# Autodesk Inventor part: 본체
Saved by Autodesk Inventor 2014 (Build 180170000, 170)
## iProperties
Created: 2026-09
Part Number: 본체
Material: 일반
Document SubType Name: Modeling
Designer: dg
Density: 1 g/cm^3
Appearance: 기본값
Author: dg
Author: jhkim
Creation Date: 2026-08-26
Sending System: Autodesk Inventor 2027
Preprocessor: ST-DEVELOPER v20.1
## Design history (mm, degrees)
node "본체1"
node "솔리드1"
node "기준1"
